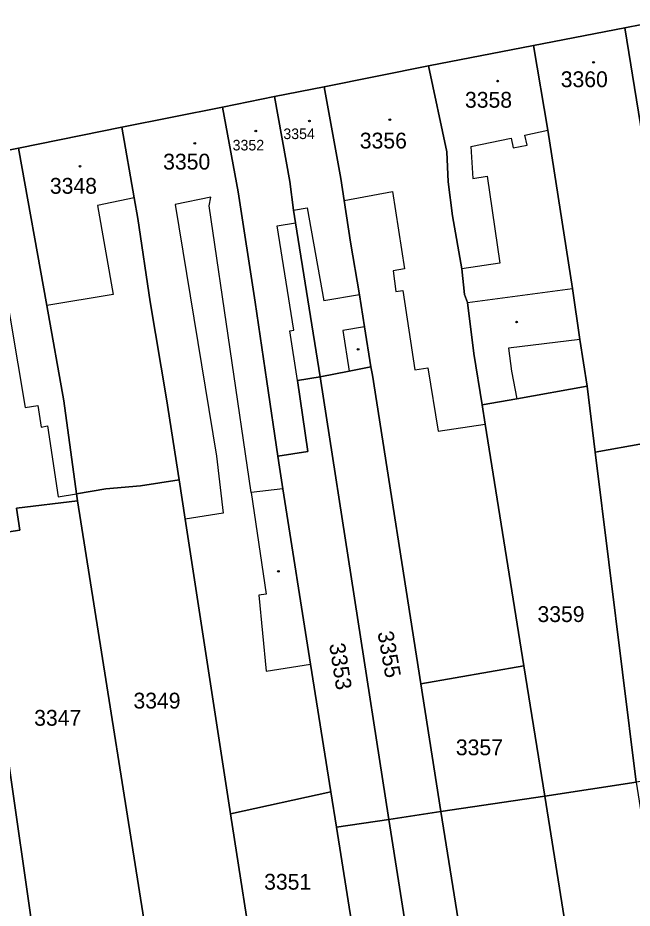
# Model space of a CAD drawing. Extents: x -596233 to -595156, y -1161235 to -1159375.
# Drawn here: x -595555.1 to -595489.1, y -1161138.1 to -1161042.5 of the extents above; entities that cross this region are included whole.
import ezdxf

# ---------------------------------------------------------------- set-up
doc = ezdxf.new("R2010")
doc.units = 0
for name, color, linetype in [('KN_CAR_KR', 7, 'Continuous'), ('KN_KULTURY', 7, 'Continuous'), ('KN_PARC_CIS_POZ', 7, 'Continuous'), ('KN_PARC_CIS_STAV', 7, 'Continuous'), ('KN_PARC_PLOCHA', 7, 'Continuous'), ('parcely_l', 7, 'Continuous')]:
    doc.layers.add(name, color=color, linetype=linetype)

msp = doc.modelspace()

# ---------------------------------------------------------------- linework, layer by layer
at = {"layer": 'KN_CAR_KR'}
for points in [[(-595500.63, -1161055.09), (-595498.16, -1161054.57)], [(-595506.43, -1161056.32), (-595502.12, -1161055.41)], [(-595502.12, -1161055.41), (-595501.9, -1161056.47)], [(-595500.41, -1161056.16), (-595500.63, -1161055.09)], [(-595506.43, -1161056.32), (-595506.23, -1161059.74)], [(-595501.9, -1161056.47), (-595500.41, -1161056.16)], [(-595506.23, -1161059.74), (-595504.69, -1161059.51)], [(-595504.69, -1161059.51), (-595503.32, -1161068.86)], [(-595520.06, -1161062.12), (-595514.88, -1161061.16)], [(-595514.88, -1161061.16), (-595513.57, -1161069.46)], [(-595542.62, -1161061.84), (-595546.57, -1161062.64)], [(-595534.4, -1161061.77), (-595538.22, -1161062.54)], [(-595538.22, -1161062.54), (-595533.79, -1161089.58)], [(-595534.56, -1161062.7), (-595534.4, -1161061.77)], [(-595546.57, -1161062.64), (-595544.87, -1161072.23)], [(-595530.05, -1161093.49), (-595534.56, -1161062.7)], [(-595525.49, -1161063.15), (-595524.05, -1161062.89)], [(-595524.05, -1161062.89), (-595522.24, -1161072.89)], [(-595527.25, -1161064.84), (-595525.27, -1161064.53)], [(-595525.48, -1161076.05), (-595527.25, -1161064.84)], [(-595503.32, -1161068.86), (-595507.4, -1161069.46)], [(-595556.75, -1161070.07), (-595554.33, -1161084.34)], [(-595513.57, -1161069.46), (-595514.81, -1161069.66)], [(-595514.81, -1161069.66), (-595514.5, -1161071.9)], [(-595514.5, -1161071.9), (-595513.76, -1161071.79)], [(-595513.76, -1161071.79), (-595512.45, -1161080.3)], [(-595506.82, -1161073.06), (-595495.52, -1161071.58)], [(-595544.87, -1161072.23), (-595552.01, -1161073.41)], [(-595518.42, -1161072.26), (-595522.24, -1161072.89)], [(-595517.86, -1161075.7), (-595520.19, -1161076.08)], [(-595525.9, -1161076.12), (-595525.48, -1161076.05)], [(-595525.07, -1161081.47), (-595525.9, -1161076.12)], [(-595520.19, -1161076.08), (-595519.52, -1161080.44)], [(-595494.73, -1161077.04), (-595502.4, -1161077.99)], [(-595502.4, -1161077.99), (-595502.09, -1161080.46)], [(-595512.45, -1161080.3), (-595511.07, -1161080.1)], [(-595511.07, -1161080.1), (-595509.96, -1161086.91)], [(-595502.09, -1161080.46), (-595501.52, -1161083.41)], [(-595554.33, -1161084.34), (-595552.96, -1161084.13)], [(-595552.96, -1161084.13), (-595552.61, -1161086.45)], [(-595552.61, -1161086.45), (-595551.92, -1161086.34)], [(-595551.92, -1161086.34), (-595550.78, -1161093.94)], [(-595509.96, -1161086.91), (-595504.9, -1161086.16)], [(-595533.79, -1161089.58), (-595533.06, -1161095.72)], [(-595526.65, -1161093.09), (-595530.05, -1161093.49)], [(-595550.78, -1161093.94), (-595548.82, -1161093.64)], [(-595530.05, -1161093.49), (-595528.45, -1161104.4)], [(-595533.06, -1161095.72), (-595537.14, -1161096.35)], [(-595528.45, -1161104.4), (-595529.22, -1161104.52)], [(-595529.22, -1161104.52), (-595528.43, -1161112.68)], [(-595528.43, -1161112.68), (-595523.66, -1161111.92)]]:
    msp.add_lwpolyline(points, dxfattribs=at)
at = {"layer": 'KN_KULTURY'}
for centre, radius in [((-595493.26, -1161047.28), 0.09), ((-595493.26, -1161047.28), 0.0398), ((-595503.57, -1161049.29), 0.09), ((-595503.57, -1161049.29), 0.0398), ((-595523.79, -1161053.57), 0.09), ((-595523.79, -1161053.57), 0.0398), ((-595515.15, -1161053.44), 0.09), ((-595515.15, -1161053.44), 0.0398), ((-595529.55, -1161054.65), 0.09), ((-595529.55, -1161054.65), 0.0398), ((-595536.11, -1161055.98), 0.09), ((-595536.11, -1161055.98), 0.0398), ((-595548.44, -1161058.43), 0.09), ((-595548.44, -1161058.43), 0.0398), ((-595501.53, -1161075.17), 0.09), ((-595501.53, -1161075.17), 0.0398), ((-595518.56, -1161078.1), 0.09), ((-595518.56, -1161078.1), 0.0398), ((-595527.12, -1161101.95), 0.09), ((-595527.12, -1161101.95), 0.0398)]:
    msp.add_circle(centre, radius, dxfattribs=at)
at = {"layer": 'KN_PARC_PLOCHA'}
msp.add_lwpolyline([(-595484.41, -1161042.49), (-595489.91, -1161043.55), (-595499.7, -1161045.45), (-595511, -1161047.65), (-595522.2, -1161049.89), (-595527.53, -1161050.96), (-595533.12, -1161052.08), (-595543.95, -1161054.25), (-595555.06, -1161056.48), (-595566.16, -1161058.7), (-595577.1, -1161061.5), (-595588.01, -1161064), (-595599.13, -1161067.3), (-595610.09, -1161070.58), (-595621.16, -1161073.65)], dxfattribs=at)
for points in [[(-595481.46, -1161059.44), (-595480.99, -1161062.17), (-595480.45, -1161065.64), (-595486.09, -1161066.86), (-595486.73, -1161063), (-595489.91, -1161043.55), (-595484.41, -1161042.49), (-595482.83, -1161051.56), (-595482.16, -1161055.42)], [(-595486.09, -1161066.86), (-595485.15, -1161072.49), (-595482.69, -1161087.28), (-595493.08, -1161089.14), (-595493.96, -1161082.06), (-595494.73, -1161077.04), (-595495.52, -1161071.58), (-595498.16, -1161054.57), (-595499.7, -1161045.45), (-595489.91, -1161043.55), (-595486.73, -1161063)], [(-595493.96, -1161082.06), (-595501.52, -1161083.41), (-595505.23, -1161084.08), (-595506.11, -1161078.55), (-595506.82, -1161073.06), (-595507.14, -1161072.21), (-595507.4, -1161069.46), (-595508.43, -1161063.77), (-595508.87, -1161060.12), (-595509.02, -1161056.87), (-595511, -1161047.65), (-595499.7, -1161045.45), (-595498.16, -1161054.57), (-595495.52, -1161071.58), (-595494.73, -1161077.04)], [(-595505.23, -1161084.08), (-595504.9, -1161086.16), (-595500.74, -1161112.12), (-595511.81, -1161114.03), (-595517, -1161080.88), (-595517.18, -1161079.99), (-595517.86, -1161075.7), (-595518.42, -1161072.26), (-595519.36, -1161066.59), (-595520.06, -1161062.12), (-595520.42, -1161059.76), (-595522.2, -1161049.89), (-595511, -1161047.65), (-595509.02, -1161056.87), (-595508.87, -1161060.12), (-595508.43, -1161063.77), (-595507.4, -1161069.46), (-595507.14, -1161072.21), (-595506.82, -1161073.06), (-595506.11, -1161078.55)], [(-595517.18, -1161079.99), (-595519.52, -1161080.44), (-595522.64, -1161081.05), (-595525.27, -1161064.53), (-595525.49, -1161063.15), (-595525.9, -1161060.07), (-595527.53, -1161050.96), (-595522.2, -1161049.89), (-595520.42, -1161059.76), (-595520.06, -1161062.12), (-595519.36, -1161066.59), (-595518.42, -1161072.26), (-595517.86, -1161075.7)], [(-595522.64, -1161081.05), (-595525.07, -1161081.47), (-595523.95, -1161089.07), (-595527.19, -1161089.58), (-595528.35, -1161081.55), (-595529.61, -1161073.02), (-595531.46, -1161061.18), (-595533.12, -1161052.08), (-595527.53, -1161050.96), (-595525.9, -1161060.07), (-595525.49, -1161063.15), (-595525.27, -1161064.53)], [(-595527.19, -1161089.58), (-595527.02, -1161090.78), (-595526.65, -1161093.09), (-595523.66, -1161111.92), (-595521.48, -1161125.65), (-595532.26, -1161128.02), (-595537.14, -1161096.35), (-595537.79, -1161092.13), (-595539.13, -1161083.43), (-595540.91, -1161072.99), (-595542.23, -1161064.05), (-595542.62, -1161061.84), (-595543.95, -1161054.25), (-595533.12, -1161052.08), (-595531.46, -1161061.18), (-595529.61, -1161073.02), (-595528.35, -1161081.55)], [(-595537.79, -1161092.13), (-595541.94, -1161092.77), (-595545.66, -1161093.09), (-595548.82, -1161093.64), (-595550.17, -1161083.63), (-595552.01, -1161073.41), (-595555.06, -1161056.48), (-595543.95, -1161054.25), (-595542.62, -1161061.84), (-595542.23, -1161064.05), (-595540.91, -1161072.99), (-595539.13, -1161083.43)], [(-595548.82, -1161093.64), (-595548.71, -1161094.38), (-595555.25, -1161095.15), (-595554.92, -1161097.54), (-595558.5, -1161098.06), (-595557.19, -1161107.2), (-595558.32, -1161107.36), (-595558.77, -1161104.18), (-595559.63, -1161098.22), (-595559.81, -1161096.99), (-595561.72, -1161082.7), (-595563.74, -1161069.64), (-595564.08, -1161067.26), (-595566.16, -1161058.7), (-595555.06, -1161056.48), (-595552.01, -1161073.41), (-595550.17, -1161083.63)], [(-595511.81, -1161114.03), (-595509.66, -1161127.76), (-595515.27, -1161128.61), (-595522.64, -1161081.05), (-595519.52, -1161080.44), (-595517.18, -1161079.99), (-595517, -1161080.88)], [(-595515.27, -1161128.61), (-595520.88, -1161129.45), (-595521.48, -1161125.65), (-595523.66, -1161111.92), (-595526.65, -1161093.09), (-595527.02, -1161090.78), (-595527.19, -1161089.58), (-595523.95, -1161089.07), (-595525.07, -1161081.47), (-595522.64, -1161081.05)], [(-595558.77, -1161104.18), (-595558.32, -1161107.36), (-595551.37, -1161155.6), (-595556.81, -1161156.4), (-595562.25, -1161157.2), (-595564.28, -1161144.11), (-595571.86, -1161092.83), (-595571.97, -1161092.07), (-595573.34, -1161082.82), (-595570.92, -1161082.46), (-595568.89, -1161082.16), (-595566.17, -1161101.93), (-595565.75, -1161105.01)], [(-595493.08, -1161089.14), (-595488.69, -1161124.61), (-595498.51, -1161126.09), (-595500.74, -1161112.12), (-595504.9, -1161086.16), (-595505.23, -1161084.08), (-595501.52, -1161083.41), (-595493.96, -1161082.06)], [(-595476.76, -1161122.82), (-595482.73, -1161123.72), (-595488.69, -1161124.61), (-595493.08, -1161089.14), (-595482.69, -1161087.28)], [(-595532.26, -1161128.02), (-595529.53, -1161145.71), (-595540.28, -1161147.46), (-595548.71, -1161094.38), (-595548.82, -1161093.64), (-595545.66, -1161093.09), (-595541.94, -1161092.77), (-595537.79, -1161092.13), (-595537.14, -1161096.35)], [(-595540.28, -1161147.46), (-595539.46, -1161153.84), (-595545.74, -1161154.77), (-595551.37, -1161155.6), (-595558.32, -1161107.36), (-595557.19, -1161107.2), (-595558.5, -1161098.06), (-595554.92, -1161097.54), (-595555.25, -1161095.15), (-595548.71, -1161094.38)], [(-595498.51, -1161126.09), (-595509.66, -1161127.76), (-595511.81, -1161114.03), (-595500.74, -1161112.12)], [(-595482.36, -1161164.84), (-595481.33, -1161171.4), (-595480.33, -1161177.72), (-595479.95, -1161180.14), (-595484.88, -1161180.9), (-595483.98, -1161186.24), (-595488.76, -1161187.13), (-595489.53, -1161182.4), (-595489.8, -1161180.72), (-595498.51, -1161126.09), (-595488.69, -1161124.61)], [(-595520.88, -1161129.45), (-595518.58, -1161143.92), (-595529.53, -1161145.71), (-595532.26, -1161128.02), (-595521.48, -1161125.65)], [(-595489.8, -1161180.72), (-595496.99, -1161181.89), (-595500.89, -1161182.57), (-595501.58, -1161178.29), (-595502.71, -1161171.2), (-595509.66, -1161127.76), (-595498.51, -1161126.09)], [(-595502.71, -1161171.2), (-595508.38, -1161172.23), (-595515.27, -1161128.61), (-595509.66, -1161127.76)], [(-595508.38, -1161172.23), (-595513.8, -1161173.22), (-595518.58, -1161143.92), (-595520.88, -1161129.45), (-595515.27, -1161128.61)]]:
    msp.add_lwpolyline(points, close=True, dxfattribs=at)
at = {"layer": 'parcely_l'}
for points in [[(-595484.41, -1161042.49), (-595489.91, -1161043.55)], [(-595499.7, -1161045.45), (-595489.91, -1161043.55)], [(-595489.91, -1161043.55), (-595486.73, -1161063), (-595486.09, -1161066.86)], [(-595499.7, -1161045.45), (-595511, -1161047.65)], [(-595493.96, -1161082.06), (-595494.73, -1161077.04), (-595495.52, -1161071.58), (-595498.16, -1161054.57), (-595499.7, -1161045.45)], [(-595511, -1161047.65), (-595522.2, -1161049.89)], [(-595505.23, -1161084.08), (-595506.11, -1161078.55), (-595506.82, -1161073.06), (-595507.14, -1161072.21), (-595507.4, -1161069.46), (-595508.43, -1161063.77), (-595508.87, -1161060.12), (-595509.02, -1161056.87), (-595511, -1161047.65)], [(-595527.53, -1161050.96), (-595522.2, -1161049.89)], [(-595522.2, -1161049.89), (-595520.42, -1161059.76), (-595520.06, -1161062.12), (-595519.36, -1161066.59), (-595518.42, -1161072.26), (-595517.86, -1161075.7), (-595517.18, -1161079.99)], [(-595527.53, -1161050.96), (-595533.12, -1161052.08)], [(-595522.64, -1161081.05), (-595525.27, -1161064.53), (-595525.49, -1161063.15), (-595525.9, -1161060.07), (-595527.53, -1161050.96)], [(-595533.12, -1161052.08), (-595543.95, -1161054.25)], [(-595533.12, -1161052.08), (-595531.46, -1161061.18), (-595529.61, -1161073.02), (-595528.35, -1161081.55), (-595527.19, -1161089.58)], [(-595543.95, -1161054.25), (-595555.06, -1161056.48)], [(-595543.95, -1161054.25), (-595542.62, -1161061.84), (-595542.23, -1161064.05), (-595540.91, -1161072.99), (-595539.13, -1161083.43), (-595537.79, -1161092.13)], [(-595555.06, -1161056.48), (-595566.16, -1161058.7)], [(-595548.82, -1161093.64), (-595550.17, -1161083.63), (-595552.01, -1161073.41), (-595555.06, -1161056.48)], [(-595517.18, -1161079.99), (-595519.52, -1161080.44), (-595522.64, -1161081.05)], [(-595517.18, -1161079.99), (-595517, -1161080.88), (-595511.81, -1161114.03)], [(-595527.19, -1161089.58), (-595523.95, -1161089.07), (-595525.07, -1161081.47), (-595522.64, -1161081.05)], [(-595515.27, -1161128.61), (-595522.64, -1161081.05)], [(-595493.96, -1161082.06), (-595501.52, -1161083.41), (-595505.23, -1161084.08)], [(-595493.08, -1161089.14), (-595493.96, -1161082.06)], [(-595505.23, -1161084.08), (-595504.9, -1161086.16), (-595500.74, -1161112.12)], [(-595482.69, -1161087.28), (-595493.08, -1161089.14)], [(-595488.69, -1161124.61), (-595493.08, -1161089.14)], [(-595521.48, -1161125.65), (-595523.66, -1161111.92), (-595526.65, -1161093.09), (-595527.02, -1161090.78), (-595527.19, -1161089.58)], [(-595548.82, -1161093.64), (-595545.66, -1161093.09), (-595541.94, -1161092.77), (-595537.79, -1161092.13)], [(-595537.79, -1161092.13), (-595537.14, -1161096.35), (-595532.26, -1161128.02)], [(-595548.71, -1161094.38), (-595548.82, -1161093.64)], [(-595558.32, -1161107.36), (-595557.19, -1161107.2), (-595558.5, -1161098.06), (-595554.92, -1161097.54), (-595555.25, -1161095.15), (-595548.71, -1161094.38)], [(-595548.71, -1161094.38), (-595540.28, -1161147.46)], [(-595551.37, -1161155.6), (-595558.32, -1161107.36)], [(-595511.81, -1161114.03), (-595500.74, -1161112.12)], [(-595500.74, -1161112.12), (-595498.51, -1161126.09)], [(-595511.81, -1161114.03), (-595509.66, -1161127.76)], [(-595498.51, -1161126.09), (-595488.69, -1161124.61)], [(-595532.26, -1161128.02), (-595521.48, -1161125.65)], [(-595520.88, -1161129.45), (-595521.48, -1161125.65)], [(-595498.51, -1161126.09), (-595509.66, -1161127.76)], [(-595489.8, -1161180.72), (-595498.51, -1161126.09)], [(-595532.26, -1161128.02), (-595529.53, -1161145.71)], [(-595509.66, -1161127.76), (-595515.27, -1161128.61)], [(-595509.66, -1161127.76), (-595502.71, -1161171.2)], [(-595515.27, -1161128.61), (-595520.88, -1161129.45)], [(-595520.88, -1161129.45), (-595518.58, -1161143.92)], [(-595508.38, -1161172.23), (-595515.27, -1161128.61)]]:
    msp.add_lwpolyline(points, dxfattribs=at)

# ---------------------------------------------------------------- texts
at = {"layer": 'KN_PARC_CIS_POZ'}
for s, p in [('3359', (-595499.2866, -1161107.4)), ('3349', (-595542.6966, -1161116.69)), ('3347', (-595553.3666, -1161118.54)), ('3357', (-595508.0566, -1161121.71)), ('3351', (-595528.6566, -1161136.15))]:
    msp.add_text(s, height=1.7, dxfattribs=at).set_placement(p)
for s, rotation, p in [('3355', 280.007004, (-595516.4816, -1161108.5208)), ('3353', 278.9714, (-595521.676, -1161109.7915))]:
    msp.add_text(s, height=1.7, rotation=rotation, dxfattribs=at).set_placement(p)
at = {"layer": 'KN_PARC_CIS_STAV'}
for s, height, p in [('3360', 1.7, (-595496.7866, -1161049.94)), ('3358', 1.7, (-595507.0766, -1161052.15)), ('3354', 1.14, (-595526.595, -1161055.52)), ('3356', 1.7, (-595518.3766, -1161056.53)), ('3352', 1.14, (-595532.045, -1161056.74)), ('3350', 1.7, (-595539.5066, -1161058.79)), ('3348', 1.7, (-595551.6766, -1161061.39))]:
    msp.add_text(s, height=height, dxfattribs=at).set_placement(p)

doc.saveas('drawing.dxf')
